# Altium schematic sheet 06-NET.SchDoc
size A4
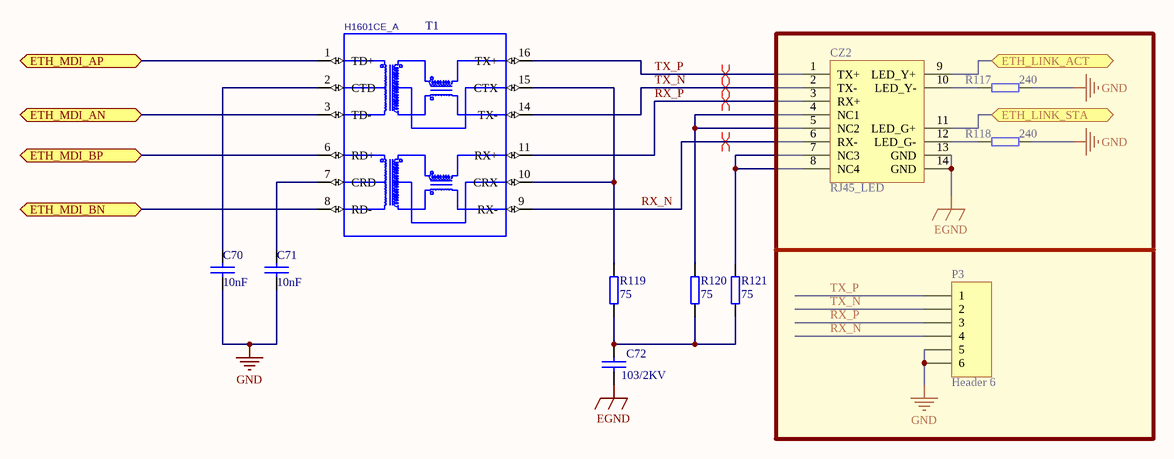
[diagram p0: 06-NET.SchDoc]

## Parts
C70  10nF  [C0402]
C71  10nF  [C0402]
C72  103/2KV  [1206C]
CZ2  RJ45_LED  [RJ45_LED]
P3  Header 6  [PH-1.25-4P]
R117  240  [R0402]
R118  240  [R0402]
R119  75  [R0402]
R120  75  [R0402]
R121  75  [R0402]
T1  DEVICE: H1601CE_A  [STFM16-50-2990]  (hidden comment: 000-7090-37R)

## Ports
ETH_LINK_ACT (bidir), ETH_LINK_STA (bidir), ETH_MDI_AN (bidir), ETH_MDI_AP (bidir), ETH_MDI_BN (bidir), ETH_MDI_BP (bidir)

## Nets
EGND: C72.2 CZ2.13(GND) CZ2.14(GND)
GND: C70.2 C71.2 P3.5 P3.6 R117.1 R118.1
ETH_LINK_ACT: CZ2.9(LED_Y+) ; port ETH_LINK_ACT
ETH_LINK_STA: CZ2.11(LED_G+) ; port ETH_LINK_STA
ETH_MDI_AN: T1.3(TD-) ; port ETH_MDI_AN
ETH_MDI_AP: T1.1(TD+) ; port ETH_MDI_AP
ETH_MDI_BN: T1.8(RD-) ; port ETH_MDI_BN
ETH_MDI_BP: T1.6(RD+) ; port ETH_MDI_BP
RX_N: CZ2.6(RX-) P3.4 T1.9(RX-)
RX_P: CZ2.3(RX+) P3.3 T1.11(RX+)
TX_N: CZ2.2(TX-) P3.2 T1.14(TX-)
TX_P: CZ2.1(TX+) P3.1 T1.16(TX+)
NetC70_1: C70.1 T1.2(CTD)
NetC71_1: C71.1 T1.7(CRD)
NetC72_1: C72.1 R119.1 R120.1 R121.1
NetCZ2_4: CZ2.4(NC1) CZ2.5(NC2) R120.2
NetCZ2_7: CZ2.7(NC3) CZ2.8(NC4) R121.2
NetCZ2_10: CZ2.10(LED_Y-) R117.2
NetCZ2_12: CZ2.12(LED_G-) R118.2
NetR119_2: R119.2 T1.10(CRX) T1.15(CTX)

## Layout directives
differential pair: RX_N, RX_P, TX_N, TX_P

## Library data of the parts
C70-C72 = 电容: Capacitor
CZ2 = RJ-45_LED: RJ-45带灯
P3 = Header 6: Header, 6-Pin
R117-R121 = 电阻Ω: Resistor
T1 = 000-7090-37R: PARTS: 1; LEVEL: STD; NC: 4,5,12,13; OriginalSymbolOrigin: (0,0); CODE: 9050179; %195%%232%%202%%246%: LAN变压器-1:1-0.35MH-1-2-100BASE-T接口模块-SMT; COMPONENT_HIGH_MAX: 6.4MM; PKG_TYPE: STFM16-50-299; %208%%161%%192%%224%%195%%251%%179%%198%: LAN变压器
